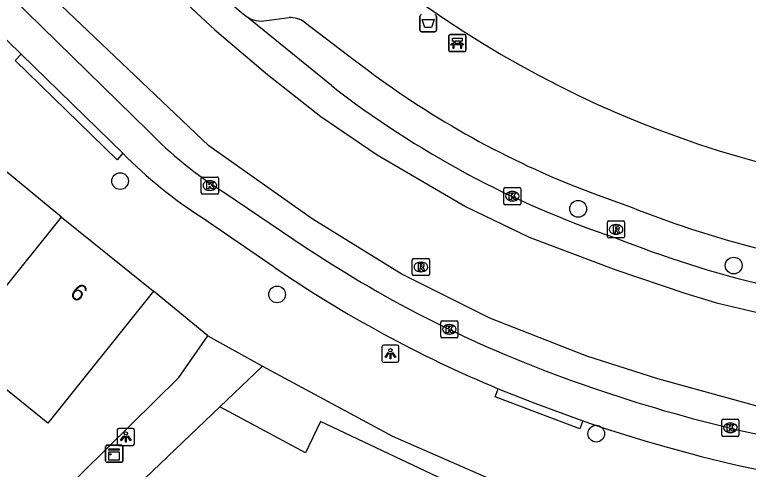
# Model space of a CAD drawing. Extents: x 162880 to 165536, y 384011 to 385179.
# Drawn here: x 164104.18 to 164147.15, y 384290.92 to 384317.52 of the extents above; entities that cross this region are included whole.
import ezdxf

# ---------------------------------------------------------------- set-up
doc = ezdxf.new("R2010")
doc.units = 0
for name, color, linetype in [('IMGEO_Afvalbak', 7, 'Continuous'), ('IMGEO_Bank', 7, 'Continuous'), ('IMGEO_Boom', 7, 'Continuous'), ('IMGEO_Kast', 7, 'Continuous'), ('IMGEO_Kolk', 7, 'Continuous'), ('IMGEO_Lichtpunt', 7, 'Continuous'), ('IMGEO_Muur', 7, 'Continuous'), ('IMGEO_Pand', 7, 'Continuous'), ('IMGEO_Pand_nummerreeks', 7, 'Continuous'), ('IMGEO_Rijbaan_lokaal_gesloten', 7, 'Continuous'), ('IMGEO_Rioolput', 7, 'Continuous'), ('IMGEO_Voetpad_open', 7, 'Continuous')]:
    doc.layers.add(name, color=color, linetype=linetype)

msp = doc.modelspace()

# ---------------------------------------------------------------- linework, layer by layer
at = {"layer": 'IMGEO_Afvalbak'}
for p, q in [((164127.903, 384316.616), (164127.903, 384317.416)), ((164127.903, 384317.416), (164127.903, 384316.616)), ((164128.893, 384317.416), (164128.893, 384316.616)), ((164128.893, 384316.616), (164128.893, 384317.416)), ((164128.793, 384316.516), (164128.003, 384316.516)), ((164128.003, 384316.516), (164128.793, 384316.516))]:
    msp.add_line(p, q, dxfattribs=at)
msp.add_lwpolyline([(164128.046, 384317.23), (164128.75, 384317.23), (164128.601, 384316.76), (164128.195, 384316.76), (164128.046, 384317.23)], dxfattribs=at)
for centre, start, end in [((164128.003, 384317.416), 90, 180), ((164128.003, 384317.416), 90, 180), ((164128.793, 384317.416), 0, 90), ((164128.793, 384317.416), 360, 90), ((164128.003, 384316.616), 180, 270), ((164128.003, 384316.616), 180, 270), ((164128.793, 384316.616), 270, 0), ((164128.793, 384316.616), 270, 0)]:
    msp.add_arc(centre, 0.1, start, end, dxfattribs=at)
at = {"layer": 'IMGEO_Bank'}
for p, q in [((164129.6, 384315.429), (164129.6, 384316.27)), ((164129.6, 384316.27), (164129.6, 384315.429)), ((164129.675, 384316.354), (164130.516, 384316.354)), ((164130.516, 384316.354), (164129.675, 384316.354)), ((164130.6, 384316.279), (164130.6, 384315.438)), ((164130.6, 384315.438), (164130.6, 384316.279)), ((164130.297, 384315.752), (164129.904, 384315.752)), ((164129.909, 384315.86), (164129.909, 384315.966)), ((164129.953, 384315.966), (164129.953, 384315.86)), ((164130.241, 384315.972), (164129.959, 384315.972)), ((164129.959, 384315.854), (164130.241, 384315.854)), ((164130.247, 384315.86), (164130.247, 384315.966)), ((164130.291, 384315.966), (164130.291, 384315.86)), ((164130.525, 384315.354), (164129.684, 384315.354)), ((164129.684, 384315.354), (164130.525, 384315.354))]:
    msp.add_line(p, q, dxfattribs=at)
for points in [[(164129.903, 384315.972), (164129.817, 384315.972), (164129.817, 384316.133), (164130.38, 384316.133), (164130.38, 384315.972), (164130.297, 384315.972)], [(164129.847, 384315.752), (164129.705, 384315.752), (164129.817, 384315.854), (164129.903, 384315.854)], [(164129.897, 384315.745), (164129.897, 384315.538), (164129.854, 384315.538), (164129.854, 384315.745)], [(164130.297, 384315.854), (164130.38, 384315.854), (164130.492, 384315.752), (164130.353, 384315.752)], [(164130.347, 384315.745), (164130.347, 384315.538), (164130.303, 384315.538), (164130.303, 384315.745)]]:
    msp.add_lwpolyline(points, dxfattribs=at)
for centre, radius, start, end in [((164129.678, 384316.276), 0.0779, 92.4484, 184.2845), ((164129.678, 384316.276), 0.0779, 92.4484, 184.2845), ((164130.522, 384316.276), 0.0779, 2.4484, 94.2845), ((164130.522, 384316.276), 0.0779, 2.4484, 94.2845), ((164129.847, 384315.745), 0.00671, 2.8957, 87.1043), ((164129.904, 384315.745), 0.00671, 92.8957, 177.1043), ((164129.902, 384315.965), 0.00671, 2.8957, 87.1043), ((164129.902, 384315.861), 0.00671, 272.8957, 357.1043), ((164129.959, 384315.965), 0.00671, 92.8957, 177.1043), ((164129.959, 384315.861), 0.00671, 182.8957, 267.1043), ((164130.241, 384315.965), 0.00671, 2.8957, 87.1043), ((164130.241, 384315.861), 0.00671, 272.8957, 357.1043), ((164130.298, 384315.965), 0.00671, 92.8957, 177.1043), ((164130.298, 384315.861), 0.00671, 182.8957, 267.1043), ((164130.296, 384315.745), 0.00671, 2.8957, 87.1043), ((164130.353, 384315.745), 0.00671, 92.8957, 177.1043), ((164129.678, 384315.432), 0.0779, 182.4484, 274.2845), ((164129.678, 384315.432), 0.0779, 182.4484, 274.2845), ((164130.522, 384315.432), 0.0779, 272.4484, 4.2845), ((164130.522, 384315.432), 0.0779, 272.4484, 4.2845)]:
    msp.add_arc(centre, radius, start, end, dxfattribs=at)
at = {"layer": 'IMGEO_Boom'}
for centre in [(164110.353, 384307.78), (164137.181, 384306.156), (164146.287, 384302.836), (164119.552, 384301.149), (164138.24, 384293)]:
    msp.add_circle(centre, 0.489, dxfattribs=at)
at = {"layer": 'IMGEO_Kast'}
for p, q in [((164109.51, 384291.403), (164109.51, 384292.244)), ((164109.51, 384292.244), (164109.51, 384291.403)), ((164109.585, 384292.328), (164110.426, 384292.328)), ((164110.426, 384292.328), (164109.585, 384292.328)), ((164110.51, 384292.253), (164110.51, 384291.412)), ((164110.51, 384291.412), (164110.51, 384292.253)), ((164110.435, 384291.328), (164109.594, 384291.328)), ((164109.594, 384291.328), (164110.435, 384291.328))]:
    msp.add_line(p, q, dxfattribs=at)
for points in [[(164109.705, 384292.118), (164110.305, 384292.118), (164110.305, 384292.033), (164109.705, 384292.033), (164109.705, 384292.118)], [(164109.705, 384291.943), (164110.305, 384291.943), (164110.305, 384291.454), (164109.705, 384291.454), (164109.705, 384291.943)]]:
    msp.add_lwpolyline(points, dxfattribs=at)
msp.add_circle((164109.789, 384291.792), 0.0377, dxfattribs=at)
for centre, start, end in [((164109.588, 384292.25), 92.4484, 184.2845), ((164109.588, 384292.25), 92.4484, 184.2845), ((164110.432, 384292.25), 2.4484, 94.2845), ((164110.432, 384292.25), 2.4484, 94.2845), ((164109.588, 384291.406), 182.4484, 274.2845), ((164109.588, 384291.406), 182.4484, 274.2845), ((164110.432, 384291.406), 272.4484, 4.2845), ((164110.432, 384291.406), 272.4484, 4.2845)]:
    msp.add_arc(centre, 0.0779, start, end, dxfattribs=at)
at = {"layer": 'IMGEO_Kolk'}
for p, q in [((164115.112, 384307.092), (164115.112, 384307.944)), ((164115.187, 384308.018), (164116.039, 384308.018)), ((164116.113, 384307.944), (164116.113, 384307.092)), ((164115.6, 384307.798), (164115.625, 384307.798)), ((164132.898, 384307.396), (164133.75, 384307.396)), ((164116.039, 384307.018), (164115.187, 384307.018)), ((164115.623, 384307.238), (164115.598, 384307.238)), ((164132.823, 384306.47), (164132.823, 384307.322)), ((164133.311, 384307.176), (164133.336, 384307.176)), ((164133.824, 384307.322), (164133.824, 384306.47)), ((164133.334, 384306.616), (164133.309, 384306.616)), ((164133.75, 384306.396), (164132.898, 384306.396)), ((164129.136, 384298.682), (164129.136, 384299.534)), ((164129.211, 384299.608), (164130.063, 384299.608)), ((164129.624, 384299.388), (164129.649, 384299.388)), ((164130.137, 384299.534), (164130.137, 384298.682)), ((164129.647, 384298.828), (164129.622, 384298.828)), ((164130.063, 384298.608), (164129.211, 384298.608)), ((164145.593, 384292.916), (164145.593, 384293.768)), ((164145.668, 384293.842), (164146.52, 384293.842)), ((164146.594, 384293.768), (164146.594, 384292.916)), ((164146.081, 384293.622), (164146.106, 384293.622)), ((164146.52, 384292.842), (164145.668, 384292.842)), ((164146.104, 384293.062), (164146.079, 384293.062))]:
    msp.add_line(p, q, dxfattribs=at)
for points in [[(164115.112, 384307.092), (164115.112, 384307.944)], [(164115.187, 384308.018), (164116.039, 384308.018)], [(164116.113, 384307.944), (164116.113, 384307.092)], [(164115.433, 384307.718), (164115.556, 384307.718), (164115.556, 384307.567), (164115.686, 384307.718), (164115.85, 384307.718), (164115.704, 384307.567), (164115.857, 384307.318), (164115.705, 384307.318), (164115.62, 384307.482), (164115.556, 384307.415), (164115.556, 384307.318), (164115.433, 384307.318), (164115.433, 384307.718)], [(164132.898, 384307.396), (164133.75, 384307.396)], [(164116.039, 384307.018), (164115.187, 384307.018)], [(164132.823, 384306.47), (164132.823, 384307.322)], [(164133.144, 384307.096), (164133.267, 384307.096), (164133.267, 384306.945), (164133.397, 384307.096), (164133.561, 384307.096), (164133.415, 384306.945), (164133.568, 384306.696), (164133.416, 384306.696), (164133.331, 384306.86), (164133.267, 384306.793), (164133.267, 384306.696), (164133.144, 384306.696), (164133.144, 384307.096)], [(164133.824, 384307.322), (164133.824, 384306.47)], [(164133.75, 384306.396), (164132.898, 384306.396)], [(164129.136, 384298.682), (164129.136, 384299.534)], [(164129.211, 384299.608), (164130.063, 384299.608)], [(164129.457, 384299.308), (164129.58, 384299.308), (164129.58, 384299.157), (164129.71, 384299.308), (164129.874, 384299.308), (164129.728, 384299.157), (164129.881, 384298.908), (164129.729, 384298.908), (164129.644, 384299.072), (164129.58, 384299.005), (164129.58, 384298.908), (164129.457, 384298.908), (164129.457, 384299.308)], [(164130.137, 384299.534), (164130.137, 384298.682)], [(164130.063, 384298.608), (164129.211, 384298.608)], [(164145.593, 384292.916), (164145.593, 384293.768)], [(164145.668, 384293.842), (164146.52, 384293.842)], [(164146.594, 384293.768), (164146.594, 384292.916)], [(164145.914, 384293.542), (164146.037, 384293.542), (164146.037, 384293.391), (164146.167, 384293.542), (164146.331, 384293.542), (164146.185, 384293.391), (164146.338, 384293.142), (164146.186, 384293.142), (164146.101, 384293.306), (164146.037, 384293.239), (164146.037, 384293.142), (164145.914, 384293.142), (164145.914, 384293.542)], [(164146.52, 384292.842), (164145.668, 384292.842)]]:
    msp.add_lwpolyline(points, dxfattribs=at)
for centre, start, end in [((164115.189, 384307.942), 91.552, 178.448), ((164115.189, 384307.942), 91.552, 178.448), ((164116.037, 384307.942), 1.552, 88.448), ((164116.037, 384307.942), 1.552, 88.448), ((164132.9, 384307.32), 91.552, 178.448), ((164132.9, 384307.32), 91.552, 178.448), ((164133.748, 384307.32), 1.552, 88.448), ((164133.748, 384307.32), 1.552, 88.448), ((164115.189, 384307.094), 181.552, 268.448), ((164115.189, 384307.094), 181.552, 268.448), ((164116.037, 384307.094), 271.552, 358.448), ((164116.037, 384307.094), 271.552, 358.448), ((164132.9, 384306.472), 181.552, 268.448), ((164132.9, 384306.472), 181.552, 268.448), ((164133.748, 384306.472), 271.552, 358.448), ((164133.748, 384306.472), 271.552, 358.448), ((164129.213, 384299.532), 91.552, 178.448), ((164129.213, 384299.532), 91.552, 178.448), ((164130.061, 384299.532), 1.552, 88.448), ((164130.061, 384299.532), 1.552, 88.448), ((164129.213, 384298.684), 181.552, 268.448), ((164129.213, 384298.684), 181.552, 268.448), ((164130.061, 384298.684), 271.552, 358.448), ((164130.061, 384298.684), 271.552, 358.448), ((164145.67, 384293.766), 91.552, 178.448), ((164145.67, 384293.766), 91.552, 178.448), ((164146.518, 384293.766), 1.552, 88.448), ((164146.518, 384293.766), 1.552, 88.448), ((164145.67, 384292.918), 181.552, 268.448), ((164145.67, 384292.918), 181.552, 268.448), ((164146.518, 384292.918), 271.552, 358.448), ((164146.518, 384292.918), 271.552, 358.448)]:
    msp.add_arc(centre, 0.0765, start, end, dxfattribs=at)
for centre, major_axis, ratio, start_param, end_param in [((164115.599, 384307.518), (-0.387, 0.002), 0.722429, 4.712389, 7.853982), ((164115.624, 384307.518), (-0.39, 0.002), 0.717154, 1.570796, 4.712389), ((164133.31, 384306.896), (-0.387, 0.002), 0.722429, 4.712389, 7.853982), ((164133.335, 384306.896), (-0.39, 0.002), 0.717154, 1.570796, 4.712389), ((164129.623, 384299.108), (-0.387, 0.002), 0.722429, 4.712389, 7.853982), ((164129.648, 384299.108), (-0.39, 0.002), 0.717154, 1.570796, 4.712389), ((164146.08, 384293.342), (-0.387, 0.002), 0.722429, 4.712389, 7.853982), ((164146.105, 384293.342), (-0.39, 0.002), 0.717154, 1.570796, 4.712389)]:
    msp.add_ellipse(centre, major_axis=major_axis, ratio=ratio, start_param=start_param, end_param=end_param, dxfattribs=at)
at = {"layer": 'IMGEO_Lichtpunt'}
for p, q in [((164125.688, 384298.085), (164125.688, 384297.278)), ((164125.688, 384298.085), (164125.688, 384297.278)), ((164126.59, 384298.18), (164125.782, 384298.18)), ((164126.59, 384298.18), (164125.782, 384298.18)), ((164126.684, 384297.278), (164126.684, 384298.085)), ((164126.684, 384297.278), (164126.684, 384298.085)), ((164125.782, 384297.184), (164126.59, 384297.184)), ((164125.782, 384297.184), (164126.59, 384297.184)), ((164110.193, 384293.217), (164110.193, 384292.41)), ((164110.193, 384293.217), (164110.193, 384292.41)), ((164111.095, 384293.312), (164110.287, 384293.312)), ((164111.095, 384293.312), (164110.287, 384293.312)), ((164111.189, 384292.41), (164111.189, 384293.217)), ((164111.189, 384292.41), (164111.189, 384293.217)), ((164110.287, 384292.316), (164111.095, 384292.316)), ((164110.287, 384292.316), (164111.095, 384292.316))]:
    msp.add_line(p, q, dxfattribs=at)
for points in [[(164126.062, 384297.749), (164126.101, 384297.721), (164125.913, 384297.459), (164125.875, 384297.486), (164126.062, 384297.749)], [(164126.164, 384297.701), (164126.211, 384297.701), (164126.211, 384297.379), (164126.164, 384297.379), (164126.164, 384297.701)], [(164126.274, 384297.721), (164126.312, 384297.748), (164126.499, 384297.486), (164126.46, 384297.458), (164126.274, 384297.721)], [(164110.567, 384292.881), (164110.606, 384292.853), (164110.418, 384292.591), (164110.38, 384292.618), (164110.567, 384292.881)], [(164110.669, 384292.833), (164110.716, 384292.833), (164110.716, 384292.511), (164110.669, 384292.511), (164110.669, 384292.833)], [(164110.779, 384292.853), (164110.817, 384292.88), (164111.004, 384292.618), (164110.965, 384292.59), (164110.779, 384292.853)]]:
    msp.add_lwpolyline(points, dxfattribs=at)
for centre in [(164126.187, 384297.883), (164110.692, 384293.015)]:
    msp.add_circle(centre, 0.0994, dxfattribs=at)
for centre, start, end in [((164125.782, 384298.085), 90, 180), ((164125.782, 384298.085), 90, 180), ((164126.59, 384298.085), 0, 90), ((164126.59, 384298.085), 0, 90), ((164125.782, 384297.278), 180, 270), ((164125.782, 384297.278), 180, 270), ((164126.59, 384297.278), 270, 0), ((164126.59, 384297.278), 270, 360), ((164110.287, 384293.217), 90, 180), ((164110.287, 384293.217), 90, 180), ((164111.095, 384293.217), 0, 90), ((164111.095, 384293.217), 0, 90), ((164110.287, 384292.41), 180, 270), ((164110.287, 384292.41), 180, 270), ((164111.095, 384292.41), 270, 0), ((164111.095, 384292.41), 270, 360)]:
    msp.add_arc(centre, 0.0946, start, end, dxfattribs=at)
at = {"layer": 'IMGEO_Muur'}
msp.add_arc((164163.663, 384368.123), 61.338, 233.66055, 271.7637, dxfattribs=at)
at = {"layer": 'IMGEO_Pand'}
for points in [[(164112.317, 384301.335), (164106.121, 384293.611), (164103.233, 384295.927), (164101.731, 384294.053), (164099.218, 384296.069), (164106.917, 384305.666)], [(164106.917, 384305.666), (164112.317, 384301.335)], [(164116.191, 384294.568), (164104.396, 384283.315), (164105.502, 384282.156)], [(164105.502, 384282.156), (164107.847, 384279.697), (164111.109, 384276.279), (164113.66, 384278.713), (164113.192, 384279.391), (164118.191, 384284.16), (164125.652, 384280.629), (164127.921, 384285.422), (164128.273, 384286.165), (164130.06, 384289.941), (164122.091, 384293.713), (164121.222, 384291.877), (164116.191, 384294.568)]]:
    msp.add_lwpolyline(points, dxfattribs=at)
at = {"layer": 'IMGEO_Rijbaan_lokaal_gesloten'}
for points in [[(164100.288, 384331.601), (164103.358, 384328.579), (164109.687, 384322.406), (164115.908, 384316.623), (164118.995, 384314.012), (164122.11, 384311.551), (164125.404, 384309.308), (164130.616, 384306.277), (164134.306, 384304.491), (164139.38, 384302.587), (164143.428, 384301.217), (164145.28, 384300.663), (164150.597, 384299.412), (164153.276, 384298.936), (164156.549, 384298.579), (164163.011, 384298.261), (164166.813, 384298.301), (164170.88, 384298.638), (164174.483, 384299.052), (164178.392, 384299.727), (164182.578, 384300.62)], [(164212.252, 384303.452), (164197.812, 384299.009), (164188.317, 384296.456), (164181.548, 384294.891), (164173.847, 384293.566), (164168.66, 384293.088), (164163.876, 384292.878), (164158.942, 384292.968), (164153.617, 384293.6), (164147.585, 384294.621), (164141.839, 384296.216), (164137.697, 384297.535), (164132.011, 384299.762), (164126.813, 384302.345), (164121.608, 384305.565), (164115.555, 384309.845), (164096.665, 384327.787)], [(164100.414, 384322.038), (164111.993, 384310.718)], [(164113.769, 384320.96), (164115.039, 384319.73), (164117.468, 384317.634), (164117.754, 384317.402)], [(164122.726, 384313.367), (164117.754, 384317.402)], [(164116.437, 384307.122), (164120.533, 384304.365)]]:
    msp.add_lwpolyline(points, dxfattribs=at)
for centre, radius, start, end in [((164157.258, 384357.883), 56.34, 232.1983, 251.477), ((164129.411, 384327.699), 24.326, 224.2729, 237.7688), ((164163.062, 384364.07), 64.147, 248.31592, 264.77683), ((164160.52, 384363.057), 71.019, 235.7334, 249.20816), ((164166.149, 384377.372), 86.4, 249.0881, 261.01948)]:
    msp.add_arc(centre, radius, start, end, dxfattribs=at)
at = {"layer": 'IMGEO_Rioolput'}
for p, q in [((164138.899, 384304.526), (164138.899, 384305.378)), ((164138.974, 384305.452), (164139.826, 384305.452)), ((164139.9, 384305.378), (164139.9, 384304.526)), ((164139.387, 384305.232), (164139.412, 384305.232)), ((164139.826, 384304.452), (164138.974, 384304.452)), ((164139.41, 384304.672), (164139.385, 384304.672)), ((164127.467, 384302.325), (164127.467, 384303.177)), ((164127.542, 384303.251), (164128.394, 384303.251)), ((164128.468, 384303.177), (164128.468, 384302.325)), ((164127.955, 384303.031), (164127.98, 384303.031)), ((164128.394, 384302.251), (164127.542, 384302.251)), ((164127.978, 384302.471), (164127.953, 384302.471))]:
    msp.add_line(p, q, dxfattribs=at)
for points in [[(164138.899, 384304.526), (164138.899, 384305.378)], [(164138.974, 384305.452), (164139.826, 384305.452)], [(164139.9, 384305.378), (164139.9, 384304.526)], [(164139.488, 384305.15), (164139.236, 384305.152), (164139.236, 384304.752)], [(164139.236, 384304.752), (164139.36, 384304.752), (164139.36, 384304.914), (164139.371, 384304.914)], [(164139.414, 384305.071), (164139.36, 384305.071), (164139.36, 384304.99)], [(164139.36, 384304.99), (164139.412, 384304.99)], [(164139.418, 384304.885), (164139.489, 384304.752), (164139.629, 384304.752), (164139.564, 384304.878)], [(164139.826, 384304.452), (164138.974, 384304.452)], [(164127.467, 384302.325), (164127.467, 384303.177)], [(164127.542, 384303.251), (164128.394, 384303.251)], [(164128.468, 384303.177), (164128.468, 384302.325)], [(164128.056, 384302.949), (164127.804, 384302.951), (164127.804, 384302.551)], [(164127.804, 384302.551), (164127.928, 384302.551), (164127.928, 384302.713), (164127.939, 384302.713)], [(164127.982, 384302.87), (164127.928, 384302.87), (164127.928, 384302.789)], [(164127.928, 384302.789), (164127.98, 384302.789)], [(164127.986, 384302.684), (164128.057, 384302.551), (164128.197, 384302.551), (164128.132, 384302.677)], [(164128.394, 384302.251), (164127.542, 384302.251)]]:
    msp.add_lwpolyline(points, dxfattribs=at)
for centre, radius, start, end in [((164138.976, 384305.376), 0.0765, 91.552, 178.448), ((164138.976, 384305.376), 0.0765, 91.552, 178.448), ((164139.824, 384305.376), 0.0765, 1.552, 88.448), ((164139.824, 384305.376), 0.0765, 1.552, 88.448), ((164139.37, 384304.861), 0.0533, 26.0293, 88.6989), ((164139.396, 384305.179), 0.19, 274.7715, 282.9687), ((164139.42, 384304.975), 0.0964, 77.0061, 93.1865), ((164139.434, 384305.032), 0.0378, 276.6634, 79.6772), ((164139.487, 384305.04), 0.109, 350.3612, 89.416), ((164139.485, 384305.04), 0.112, 277.5842, 350.9817), ((164139.469, 384304.825), 0.108, 29.5134, 73.7905), ((164138.976, 384304.528), 0.0765, 181.552, 268.448), ((164138.976, 384304.528), 0.0765, 181.552, 268.448), ((164139.824, 384304.528), 0.0765, 271.552, 358.448), ((164139.824, 384304.528), 0.0765, 271.552, 358.448), ((164127.544, 384303.175), 0.0765, 91.552, 178.448), ((164127.544, 384303.175), 0.0765, 91.552, 178.448), ((164128.392, 384303.175), 0.0765, 1.552, 88.448), ((164128.392, 384303.175), 0.0765, 1.552, 88.448), ((164127.938, 384302.66), 0.0533, 26.0293, 88.6989), ((164127.964, 384302.978), 0.19, 274.7715, 282.9687), ((164127.988, 384302.774), 0.0964, 77.0061, 93.1865), ((164128.002, 384302.831), 0.0378, 276.6634, 79.6772), ((164128.055, 384302.839), 0.109, 350.3612, 89.416), ((164128.053, 384302.839), 0.112, 277.5842, 350.9817), ((164128.037, 384302.624), 0.108, 29.5134, 73.7905), ((164127.544, 384302.327), 0.0765, 181.552, 268.448), ((164127.544, 384302.327), 0.0765, 181.552, 268.448), ((164128.392, 384302.327), 0.0765, 271.552, 358.448), ((164128.392, 384302.327), 0.0765, 271.552, 358.448)]:
    msp.add_arc(centre, radius, start, end, dxfattribs=at)
for centre, major_axis, ratio, start_param, end_param in [((164139.386, 384304.952), (-0.387, 0.002), 0.722429, 4.712389, 7.853982), ((164139.411, 384304.952), (-0.39, 0.002), 0.717154, 1.570796, 4.712389), ((164127.954, 384302.751), (-0.387, 0.002), 0.722429, 4.712389, 7.853982), ((164127.979, 384302.751), (-0.39, 0.002), 0.717154, 1.570796, 4.712389)]:
    msp.add_ellipse(centre, major_axis=major_axis, ratio=ratio, start_param=start_param, end_param=end_param, dxfattribs=at)
at = {"layer": 'IMGEO_Voetpad_open'}
for points in [[(164104.559, 384315.209), (164097.654, 384321.926), (164097.392, 384322.493), (164096.796, 384324.781)], [(164118.93, 384317.173), (164120.249, 384317.35)], [(164121.137, 384317.104), (164124.084, 384314.862)], [(164110.509, 384309.409), (164110.19, 384309.024), (164104.214, 384314.826), (164104.559, 384315.209)], [(164104.559, 384315.209), (164110.509, 384309.409)], [(164106.917, 384305.666), (164100.864, 384310.637)], [(164136.763, 384307.563), (164137.625, 384307.222), (164138.296, 384306.969), (164139.977, 384306.378)], [(164119.374, 384302.746), (164115.153, 384305.639)], [(164145.976, 384304.307), (164147.569, 384303.874)], [(164115.492, 384298.721), (164112.317, 384301.335)], [(164094.153, 384276.963), (164113.789, 384296.288), (164115.492, 384298.721)], [(164115.492, 384298.721), (164118.693, 384296.955)], [(164116.191, 384294.568), (164118.693, 384296.955)], [(164118.693, 384296.955), (164126.3, 384292.851), (164133.482, 384289.712), (164136.785, 384288.527), (164142.516, 384286.842), (164149.177, 384285.243), (164149.156, 384284.983), (164153.245, 384283.977)], [(164137.448, 384293.754), (164137.278, 384293.285), (164132.319, 384295.164), (164132.496, 384295.63)], [(164132.496, 384295.63), (164134.634, 384294.781), (164137.448, 384293.754)]]:
    msp.add_lwpolyline(points, dxfattribs=at)
for centre, radius, start, end in [((164163.663, 384368.123), 61.338, 233.66055, 271.7637), ((164118.63, 384318.768), 1.623, 237.3149, 280.6467), ((164120.295, 384315.792), 1.559, 57.3248, 91.7068), ((164156.794, 384357.02), 53.36, 232.1926, 247.9513), ((164130.252, 384328.984), 27.802, 224.7548, 237.1058), ((164162.276, 384361.247), 59.227, 247.88286, 254.02531), ((164160.389, 384362.721), 72.658, 235.63324, 247.42521), ((164165.862, 384375.853), 86.877, 250.90958, 257.8629)]:
    msp.add_arc(centre, radius, start, end, dxfattribs=at)

# ---------------------------------------------------------------- texts
at = {"layer": 'IMGEO_Pand_nummerreeks'}
msp.add_text('6', height=1, rotation=321.2691, dxfattribs=at).set_placement((164107.35, 384301.113))

doc.saveas('drawing.dxf')
